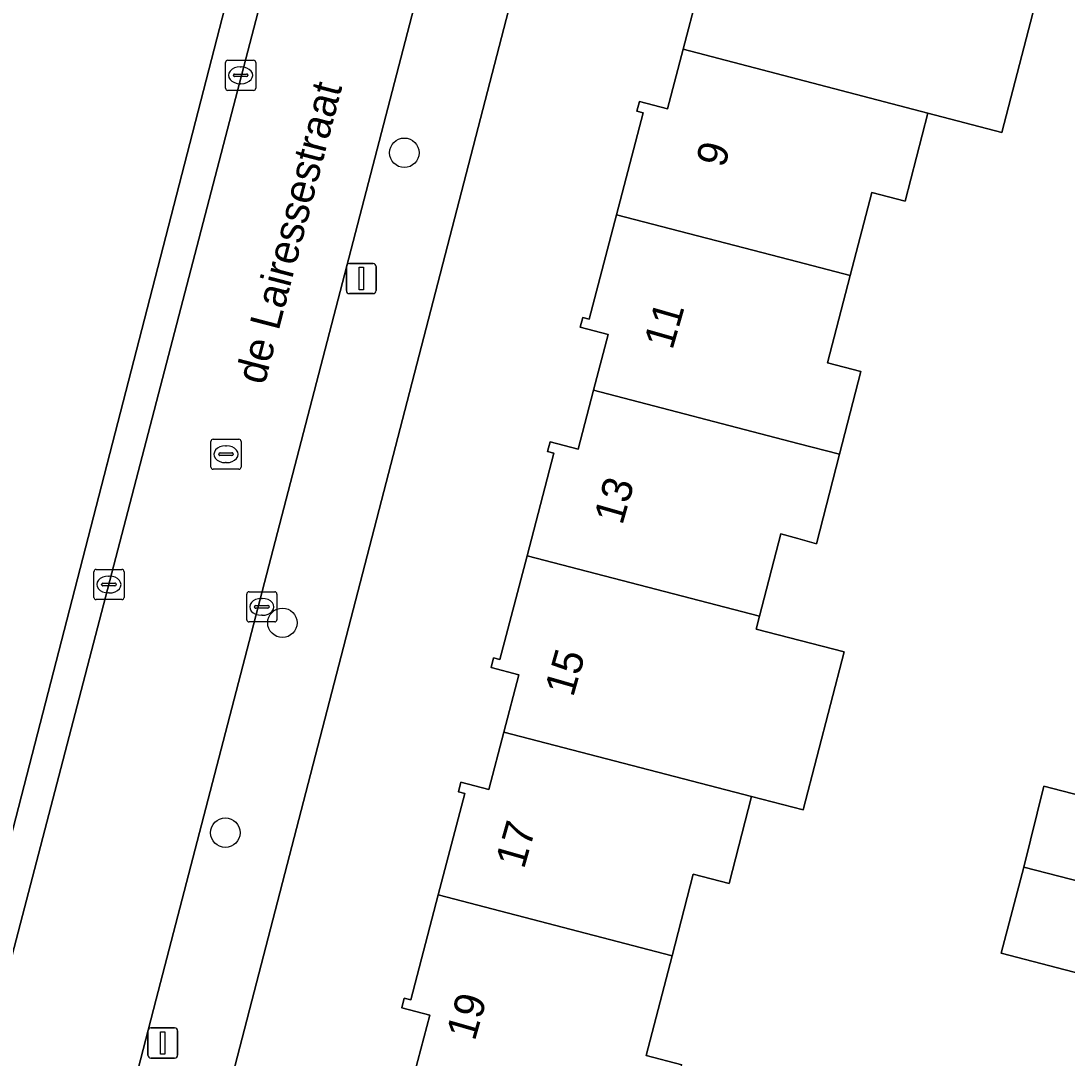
# Model space of a CAD drawing. Extents: x 163683 to 164494, y 382709 to 383872.
# Drawn here: x 163974.2 to 164008.94, y 383192.54 to 383226.97 of the extents above; entities that cross this region are included whole.
import ezdxf

# ---------------------------------------------------------------- set-up
doc = ezdxf.new("R2010")
doc.units = 0
for name, color, linetype in [('IMGEO_Boom', 7, 'Continuous'), ('IMGEO_Erf', 7, 'Continuous'), ('IMGEO_Groenvoorziening', 7, 'Continuous'), ('IMGEO_Kolk', 7, 'Continuous'), ('IMGEO_Lichtmast', 7, 'Continuous'), ('IMGEO_Openbare_ruimte_label', 7, 'Continuous'), ('IMGEO_Pand', 7, 'Continuous'), ('IMGEO_Pand_nummerreeks', 7, 'Continuous'), ('IMGEO_Rijbaan_lokaal_open', 7, 'Continuous'), ('IMGEO_Rioolput', 7, 'Continuous'), ('IMGEO_Voetpad_open', 7, 'Continuous')]:
    doc.layers.add(name, color=color, linetype=linetype)

msp = doc.modelspace()

# ---------------------------------------------------------------- linework, layer by layer
at = {"layer": 'IMGEO_Boom'}
for centre in [(163986.935, 383222.594), (163982.887, 383206.992), (163980.991, 383200.023)]:
    msp.add_circle(centre, 0.489, dxfattribs=at)
at = {"layer": 'IMGEO_Erf'}
for points in [[(163996.272, 383250), (163979.052, 383183.556)], [(164008.167, 383228.648), (164006.772, 383223.269), (164004.321, 383223.909), (164003.563, 383220.982), (164002.452, 383221.27), (164001.739, 383218.517), (164000.987, 383215.616), (164002.095, 383215.329), (164001.385, 383212.588), (164000.616, 383209.618), (164000.002, 383209.794), (163999.436, 383209.94), (163998.729, 383207.212), (163998.617, 383206.78), (164001.537, 383206.024), (164000.179, 383200.784), (163998.466, 383201.228), (163997.717, 383198.337), (163996.527, 383198.646), (163995.824, 383195.934), (163994.966, 383192.623), (163996.153, 383192.315)], [(163993.704, 383216.561), (163992.775, 383216.804), (163992.859, 383217.125), (163993.073, 383217.07), (163993.982, 383220.539), (163994.867, 383223.917), (163994.655, 383223.973), (163994.739, 383224.294), (163995.67, 383224.051), (163996.19, 383226.034), (163996.668, 383227.858)], [(163987.287, 383192.09), (163987.779, 383193.967), (163986.85, 383194.211), (163986.933, 383194.53), (163987.146, 383194.475), (163988.058, 383197.956), (163988.941, 383201.323), (163988.729, 383201.38), (163988.813, 383201.7), (163989.743, 383201.457), (163990.242, 383203.36), (163990.742, 383205.264), (163989.813, 383205.508), (163989.897, 383205.828), (163990.109, 383205.772), (163991.012, 383209.218), (163991.904, 383212.62), (163991.692, 383212.676), (163991.776, 383212.997), (163992.707, 383212.753), (163993.22, 383214.712), (163993.704, 383216.561)], [(164009.943, 383195.195), (164006.756, 383196.021), (164007.507, 383198.884), (164008.168, 383201.569), (164011.284, 383200.761)]]:
    msp.add_lwpolyline(points, dxfattribs=at)
at = {"layer": 'IMGEO_Groenvoorziening'}
msp.add_lwpolyline([(163959.522, 383246.173), (163947.735, 383201.003), (163953.035, 383199.492), (163962.651, 383196.748), (163972.339, 383193.984), (163972.786, 383195.714), (163984.169, 383239.809)], close=True, dxfattribs=at)
at = {"layer": 'IMGEO_Kolk'}
for p, q in [((163981.074, 383225.665), (163981.926, 383225.665)), ((163980.999, 383224.739), (163980.999, 383225.591)), ((163981.487, 383225.445), (163981.512, 383225.445)), ((163982, 383225.591), (163982, 383224.739)), ((163981.258, 383225.159), (163981.258, 383225.171)), ((163981.696, 383225.122), (163981.298, 383225.122)), ((163981.301, 383225.208), (163981.699, 383225.208)), ((163981.742, 383225.171), (163981.742, 383225.159)), ((163981.926, 383224.665), (163981.074, 383224.665)), ((163981.51, 383224.885), (163981.485, 383224.885)), ((163976.626, 383207.836), (163976.626, 383208.688)), ((163976.701, 383208.762), (163977.553, 383208.762)), ((163977.627, 383208.688), (163977.627, 383207.836)), ((163976.928, 383208.305), (163977.326, 383208.305)), ((163977.114, 383208.542), (163977.139, 383208.542)), ((163976.885, 383208.256), (163976.885, 383208.268)), ((163977.323, 383208.219), (163976.925, 383208.219)), ((163977.137, 383207.982), (163977.112, 383207.982)), ((163977.369, 383208.268), (163977.369, 383208.256)), ((163981.703, 383207.094), (163981.703, 383207.946)), ((163981.778, 383208.02), (163982.63, 383208.02)), ((163982.704, 383207.946), (163982.704, 383207.094)), ((163977.553, 383207.762), (163976.701, 383207.762)), ((163982.191, 383207.8), (163982.216, 383207.8)), ((163981.962, 383207.514), (163981.962, 383207.526)), ((163982.4, 383207.477), (163982.002, 383207.477)), ((163982.005, 383207.563), (163982.403, 383207.563)), ((163982.446, 383207.526), (163982.446, 383207.514)), ((163982.63, 383207.02), (163981.778, 383207.02)), ((163982.214, 383207.24), (163982.189, 383207.24))]:
    msp.add_line(p, q, dxfattribs=at)
for points in [[(163981.074, 383225.665), (163981.926, 383225.665)], [(163980.999, 383224.739), (163980.999, 383225.591)], [(163982, 383225.591), (163982, 383224.739)], [(163981.926, 383224.665), (163981.074, 383224.665)], [(163976.626, 383207.836), (163976.626, 383208.688)], [(163976.701, 383208.762), (163977.553, 383208.762)], [(163977.627, 383208.688), (163977.627, 383207.836)], [(163981.703, 383207.094), (163981.703, 383207.946)], [(163981.778, 383208.02), (163982.63, 383208.02)], [(163982.704, 383207.946), (163982.704, 383207.094)], [(163977.553, 383207.762), (163976.701, 383207.762)], [(163982.63, 383207.02), (163981.778, 383207.02)]]:
    msp.add_lwpolyline(points, dxfattribs=at)
for centre, radius, start, end in [((163981.076, 383225.589), 0.0765, 91.552, 178.448), ((163981.076, 383225.589), 0.0765, 91.552, 178.448), ((163981.924, 383225.589), 0.0765, 1.552, 88.448), ((163981.924, 383225.589), 0.0765, 1.552, 88.448), ((163981.298, 383225.168), 0.0403, 85.8775, 175.7526), ((163981.295, 383225.158), 0.0366, 178.938, 274.7102), ((163981.699, 383225.165), 0.043, 264.8664, 352.4533), ((163981.703, 383225.17), 0.0386, 1.7309, 96.639), ((163981.076, 383224.741), 0.0765, 181.552, 268.448), ((163981.076, 383224.741), 0.0765, 181.552, 268.448), ((163981.924, 383224.741), 0.0765, 271.552, 358.448), ((163981.924, 383224.741), 0.0765, 271.552, 358.448), ((163976.703, 383208.686), 0.0765, 91.552, 178.448), ((163976.703, 383208.686), 0.0765, 91.552, 178.448), ((163977.551, 383208.686), 0.0765, 1.552, 88.448), ((163977.551, 383208.686), 0.0765, 1.552, 88.448), ((163976.925, 383208.265), 0.0403, 85.8775, 175.7526), ((163977.33, 383208.267), 0.0386, 1.7309, 96.639), ((163976.922, 383208.255), 0.0366, 178.938, 274.7102), ((163977.326, 383208.262), 0.043, 264.8664, 352.4533), ((163981.78, 383207.944), 0.0765, 91.552, 178.448), ((163981.78, 383207.944), 0.0765, 91.552, 178.448), ((163982.628, 383207.944), 0.0765, 1.552, 88.448), ((163982.628, 383207.944), 0.0765, 1.552, 88.448), ((163976.703, 383207.838), 0.0765, 181.552, 268.448), ((163976.703, 383207.838), 0.0765, 181.552, 268.448), ((163977.551, 383207.838), 0.0765, 271.552, 358.448), ((163977.551, 383207.838), 0.0765, 271.552, 358.448), ((163982.002, 383207.523), 0.0403, 85.8775, 175.7526), ((163981.999, 383207.513), 0.0366, 178.938, 274.7102), ((163982.403, 383207.52), 0.043, 264.8664, 352.4533), ((163982.407, 383207.525), 0.0386, 1.7309, 96.639), ((163981.78, 383207.096), 0.0765, 181.552, 268.448), ((163981.78, 383207.096), 0.0765, 181.552, 268.448), ((163982.628, 383207.096), 0.0765, 271.552, 358.448), ((163982.628, 383207.096), 0.0765, 271.552, 358.448)]:
    msp.add_arc(centre, radius, start, end, dxfattribs=at)
for centre, major_axis, ratio, start_param, end_param in [((163981.486, 383225.165), (-0.387, 0.002), 0.722429, 4.712389, 7.853982), ((163981.511, 383225.165), (-0.39, 0.002), 0.717154, 1.570796, 4.712389), ((163977.113, 383208.262), (-0.387, 0.002), 0.722429, 4.712389, 7.853982), ((163977.138, 383208.262), (-0.39, 0.002), 0.717154, 1.570796, 4.712389), ((163982.19, 383207.52), (-0.387, 0.002), 0.722429, 4.712389, 7.853982), ((163982.215, 383207.52), (-0.39, 0.002), 0.717154, 1.570796, 4.712389)]:
    msp.add_ellipse(centre, major_axis=major_axis, ratio=ratio, start_param=start_param, end_param=end_param, dxfattribs=at)
at = {"layer": 'IMGEO_Lichtmast'}
for p, q in [((163985.011, 383218.018), (163985.011, 383218.818)), ((163985.011, 383218.818), (163985.011, 383218.018)), ((163985.111, 383218.918), (163985.901, 383218.918)), ((163985.901, 383218.918), (163985.111, 383218.918)), ((163986.001, 383218.818), (163986.001, 383218.018)), ((163986.001, 383218.018), (163986.001, 383218.818)), ((163985.901, 383217.918), (163985.111, 383217.918)), ((163985.111, 383217.918), (163985.901, 383217.918)), ((163978.418, 383192.642), (163978.418, 383193.442)), ((163978.418, 383193.442), (163978.418, 383192.642)), ((163978.518, 383193.542), (163979.308, 383193.542)), ((163979.308, 383193.542), (163978.518, 383193.542)), ((163979.408, 383193.442), (163979.408, 383192.642)), ((163979.408, 383192.642), (163979.408, 383193.442)), ((163979.308, 383192.542), (163978.518, 383192.542)), ((163978.518, 383192.542), (163979.308, 383192.542))]:
    msp.add_line(p, q, dxfattribs=at)
for points in [[(163985.431, 383218.793), (163985.581, 383218.793), (163985.581, 383218.043), (163985.431, 383218.043), (163985.431, 383218.793)], [(163978.838, 383193.417), (163978.988, 383193.417), (163978.988, 383192.667), (163978.838, 383192.667), (163978.838, 383193.417)]]:
    msp.add_lwpolyline(points, dxfattribs=at)
for centre, start, end in [((163985.111, 383218.818), 90, 180), ((163985.111, 383218.818), 90, 180), ((163985.901, 383218.818), 0, 90), ((163985.901, 383218.818), 360, 90), ((163985.111, 383218.018), 180, 270), ((163985.111, 383218.018), 180, 270), ((163985.901, 383218.018), 270, 0), ((163985.901, 383218.018), 270, 0), ((163978.518, 383193.442), 90, 180), ((163978.518, 383193.442), 90, 180), ((163979.308, 383193.442), 0, 90), ((163979.308, 383193.442), 360, 90), ((163978.518, 383192.642), 180, 270), ((163978.518, 383192.642), 180, 270), ((163979.308, 383192.642), 270, 0), ((163979.308, 383192.642), 270, 0)]:
    msp.add_arc(centre, 0.1, start, end, dxfattribs=at)
at = {"layer": 'IMGEO_Pand'}
for points in [[(164004.647, 383229.56), (164004.702, 383229.772), (164000, 383230.994), (163996.933, 383231.792), (163996.035, 383228.367), (163995.822, 383228.422), (163995.738, 383228.102), (163996.668, 383227.858), (163996.19, 383226.034), (164000, 383225.038), (164004.321, 383223.909), (164006.772, 383223.269), (164008.167, 383228.648)], [(163993.982, 383220.539), (164000, 383218.97), (164001.739, 383218.517), (164002.452, 383221.27), (164003.563, 383220.982), (164004.321, 383223.909), (164000, 383225.038), (163996.19, 383226.034), (163995.67, 383224.051), (163994.739, 383224.294), (163994.655, 383223.973), (163994.867, 383223.917)], [(163993.982, 383220.539), (163993.073, 383217.07), (163992.859, 383217.125), (163992.775, 383216.804), (163993.704, 383216.561), (163993.22, 383214.712), (164000, 383212.948), (164001.385, 383212.588), (164002.095, 383215.329), (164000.987, 383215.616), (164001.739, 383218.517), (164000, 383218.97)], [(163993.22, 383214.712), (163992.707, 383212.753), (163991.776, 383212.997), (163991.692, 383212.676), (163991.904, 383212.62), (163991.012, 383209.218), (163998.729, 383207.212), (163999.436, 383209.94), (164000.002, 383209.794), (164000.616, 383209.618), (164001.385, 383212.588), (164000, 383212.948)], [(164001.537, 383206.024), (163998.617, 383206.78), (163998.729, 383207.212), (163991.012, 383209.218), (163990.109, 383205.772), (163989.897, 383205.828), (163989.813, 383205.508), (163990.742, 383205.264), (163990.242, 383203.36), (163998.466, 383201.228), (164000.179, 383200.784)], [(163990.242, 383203.36), (163989.743, 383201.457), (163988.813, 383201.7), (163988.729, 383201.38), (163988.941, 383201.323), (163988.058, 383197.956), (163995.824, 383195.934), (163996.527, 383198.646), (163997.717, 383198.337), (163998.466, 383201.228)], [(164011.284, 383200.761), (164008.168, 383201.569), (164007.507, 383198.884), (164010.993, 383197.981), (164011.662, 383200.663)], [(164010.993, 383197.981), (164007.507, 383198.884), (164006.756, 383196.021), (164009.943, 383195.195), (164010.251, 383195.115)], [(163995.824, 383195.934), (163988.058, 383197.956), (163987.146, 383194.475), (163986.933, 383194.53), (163986.85, 383194.211), (163987.779, 383193.967), (163987.287, 383192.09), (163995.538, 383189.942), (163996.153, 383192.315), (163994.966, 383192.623)]]:
    msp.add_lwpolyline(points, close=True, dxfattribs=at)
at = {"layer": 'IMGEO_Rijbaan_lokaal_open'}
for points in [[(163997.32, 383266.127), (163997.826, 383268.081), (163998.402, 383270.223), (163998.967, 383272.399), (163999.214, 383273.325), (163996.27, 383274.082), (163994.374, 383274.569), (163992.18, 383266.025), (163991.355, 383262.889), (163988.003, 383250), (163973.782, 383195.446), (163972.206, 383189.323)], [(163975.737, 383183.058), (163978.698, 383194.496), (163997.32, 383266.127)]]:
    msp.add_lwpolyline(points, dxfattribs=at)
at = {"layer": 'IMGEO_Rioolput'}
for p, q in [((163980.513, 383212.161), (163980.513, 383213.013)), ((163980.588, 383213.087), (163981.44, 383213.087)), ((163981.001, 383212.867), (163981.026, 383212.867)), ((163981.514, 383213.013), (163981.514, 383212.161)), ((163980.772, 383212.581), (163980.772, 383212.593)), ((163981.21, 383212.544), (163980.812, 383212.544)), ((163980.815, 383212.63), (163981.213, 383212.63)), ((163981.256, 383212.593), (163981.256, 383212.581)), ((163981.024, 383212.307), (163980.999, 383212.307)), ((163981.44, 383212.087), (163980.588, 383212.087))]:
    msp.add_line(p, q, dxfattribs=at)
for points in [[(163980.513, 383212.161), (163980.513, 383213.013)], [(163980.588, 383213.087), (163981.44, 383213.087)], [(163981.514, 383213.013), (163981.514, 383212.161)], [(163981.44, 383212.087), (163980.588, 383212.087)]]:
    msp.add_lwpolyline(points, dxfattribs=at)
for centre, radius, start, end in [((163980.59, 383213.011), 0.0765, 91.552, 178.448), ((163980.59, 383213.011), 0.0765, 91.552, 178.448), ((163981.438, 383213.011), 0.0765, 1.552, 88.448), ((163981.438, 383213.011), 0.0765, 1.552, 88.448), ((163980.812, 383212.59), 0.0403, 85.8775, 175.7526), ((163980.809, 383212.58), 0.0366, 178.938, 274.7102), ((163981.213, 383212.587), 0.043, 264.8664, 352.4533), ((163981.217, 383212.592), 0.0386, 1.7309, 96.639), ((163980.59, 383212.163), 0.0765, 181.552, 268.448), ((163980.59, 383212.163), 0.0765, 181.552, 268.448), ((163981.438, 383212.163), 0.0765, 271.552, 358.448), ((163981.438, 383212.163), 0.0765, 271.552, 358.448)]:
    msp.add_arc(centre, radius, start, end, dxfattribs=at)
for centre, major_axis, ratio, start_param, end_param in [((163981, 383212.587), (-0.387, 0.002), 0.722429, 4.712389, 7.853982), ((163981.025, 383212.587), (-0.39, 0.002), 0.717154, 1.570796, 4.712389)]:
    msp.add_ellipse(centre, major_axis=major_axis, ratio=ratio, start_param=start_param, end_param=end_param, dxfattribs=at)
at = {"layer": 'IMGEO_Voetpad_open'}
for points in [[(163988.003, 383250), (163991.355, 383262.889), (163992.18, 383266.025), (163994.374, 383274.569), (163995.776, 383280.026), (163997.664, 383279.557), (163998.45, 383282.559), (163995.373, 383283.39), (163994.608, 383280.362), (163993.64, 383276.548), (163991.499, 383268.114), (163990.802, 383265.4), (163986.817, 383250), (163985.708, 383245.713), (163984.169, 383239.809), (163972.786, 383195.714), (163972.339, 383193.984), (163971.307, 383189.99), (163969.992, 383184.902), (163972.224, 383183.617)], [(163999.732, 383275.264), (163999.214, 383273.325), (163998.967, 383272.399), (163998.402, 383270.223), (163997.826, 383268.081), (163997.32, 383266.127), (163978.698, 383194.496), (163975.737, 383183.058), (163979.697, 383181.672)], [(163972.206, 383189.323), (163973.782, 383195.446), (163988.003, 383250)], [(163979.052, 383183.556), (163996.272, 383250)]]:
    msp.add_lwpolyline(points, dxfattribs=at)

# ---------------------------------------------------------------- texts
at = {"layer": 'IMGEO_Openbare_ruimte_label'}
msp.add_text('de Lairessestraat', height=1, rotation=75.408, dxfattribs=at).set_placement((163982.29, 383214.861))
msp.add_text('de Lairessestraat', height=1, rotation=75.408, dxfattribs=at).set_placement((163982.29, 383214.861))
at = {"layer": 'IMGEO_Pand_nummerreeks'}
for s, rotation, p in [('9', 74.0365, (163997.562, 383222.064)), ('11', 74.0365, (163995.834, 383216.023)), ('13', 74.0365, (163994.171, 383210.206)), ('15', 74.0376, (163992.538, 383204.498)), ('17', 74.0365, (163990.905, 383198.79)), ('19', 74.0365, (163989.272, 383193.082))]:
    msp.add_text(s, height=1, rotation=rotation, dxfattribs=at).set_placement(p)

doc.saveas('drawing.dxf')
